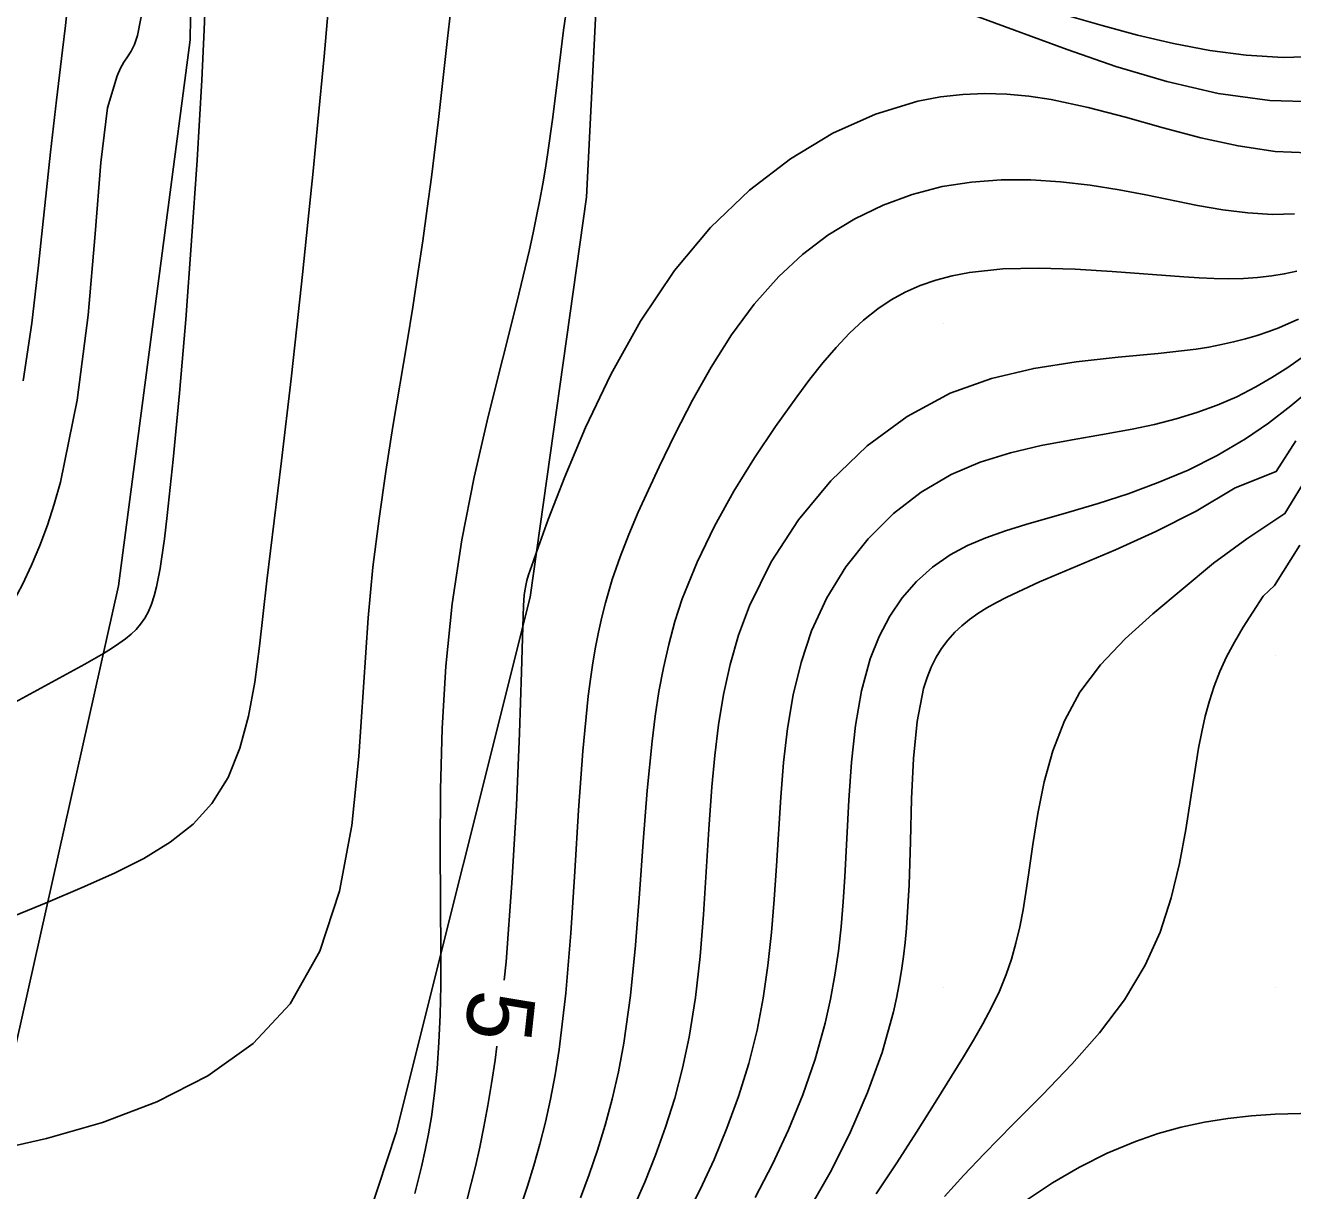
# Model space of a CAD drawing. Extents: x 2602990 to 2605851, y 618069 to 619180.
# Drawn here: x 2603422.33 to 2603460.52, y 618573.87 to 618609 of the extents above; entities that cross this region are included whole.
import ezdxf

# ---------------------------------------------------------------- set-up
doc = ezdxf.new("R2010")
doc.units = 0
for name, color, linetype in [('DTM Contours Major', 7, 'Continuous'), ('DTM Contours Minor', 7, 'Continuous'), ('DTM Contours Minor Text', 7, 'Continuous'), ('Exist DTM Crownline', 7, 'Continuous'), ('Exist DTM QL2 LIDAR Elevation Point', 7, 'Continuous'), ('Exist Roads EOP', 7, 'Continuous'), ('PH Exist DTM Breakline', 7, 'Continuous')]:
    doc.layers.add(name, color=color, linetype=linetype)

msp = doc.modelspace()

# ---------------------------------------------------------------- linework, layer by layer
at = {"layer": 'DTM Contours Major'}
msp.add_lwpolyline([(2603440.652, 618573.336), (2603440.998, 618574.125), (2603441.325, 618574.94), (2603441.627, 618575.783), (2603441.901, 618576.656), (2603442.14, 618577.56), (2603442.339, 618578.499), (2603442.527, 618579.696), (2603442.664, 618580.935), (2603442.767, 618582.202), (2603442.929, 618584.771), (2603443.021, 618586.047), (2603443.108, 618586.986), (2603443.221, 618587.912), (2603443.371, 618588.827), (2603443.57, 618589.73), (2603443.828, 618590.623), (2603444.157, 618591.505), (2603444.809, 618592.829), (2603445.631, 618594.095), (2603446.602, 618595.271), (2603447.702, 618596.321), (2603448.91, 618597.212), (2603450.207, 618597.909), (2603451.449, 618598.359), (2603452.723, 618598.662), (2603454.002, 618598.86), (2603455.261, 618598.995), (2603456.475, 618599.109), (2603457.617, 618599.244), (2603458.002, 618599.305), (2603458.377, 618599.376), (2603458.743, 618599.457), (2603459.103, 618599.549), (2603459.457, 618599.655), (2603459.807, 618599.775), (2603460.104, 618599.888), (2603460.401, 618600.013), (2603460.699, 618600.148)], dxfattribs=at)
at = {"layer": 'DTM Contours Minor'}
for points in [[(2603431.706, 618612.359), (2603431.333, 618608.062), (2603431.15, 618606.095), (2603431.004, 618604.606), (2603430.848, 618603.063), (2603430.683, 618601.491), (2603430.512, 618599.912), (2603430.338, 618598.35), (2603430.047, 618595.873), (2603429.612, 618592.259), (2603429.389, 618590.282), (2603429.247, 618589.203), (2603429.06, 618588.172), (2603428.8, 618587.207), (2603428.442, 618586.323), (2603427.956, 618585.539), (2603427.385, 618584.919), (2603426.697, 618584.376), (2603425.904, 618583.89), (2603425.017, 618583.441), (2603424.047, 618583.008), (2603423.006, 618582.571), (2603421.553, 618581.972)], [(2603421.327, 618575.073), (2603422.974, 618575.448), (2603424.653, 618575.931), (2603426.296, 618576.549), (2603427.834, 618577.332), (2603429.198, 618578.308), (2603430.317, 618579.505), (2603431.211, 618581.089), (2603431.803, 618582.904), (2603432.169, 618584.885), (2603432.384, 618586.962), (2603432.663, 618591.137), (2603432.809, 618592.668), (2603432.99, 618594.138), (2603433.194, 618595.549), (2603433.41, 618596.905), (2603433.839, 618599.459), (2603434.008, 618600.505), (2603434.164, 618601.52), (2603434.308, 618602.509), (2603434.442, 618603.477), (2603434.568, 618604.43), (2603434.781, 618606.167), (2603435.059, 618608.603), (2603435.354, 618611.228)], [(2603441.957, 618611.473), (2603442.383, 618611.443), (2603443.405, 618611.301), (2603444.481, 618611.084), (2603445.566, 618610.843), (2603446.622, 618610.59), (2603447.411, 618610.388), (2603448.173, 618610.181), (2603448.923, 618609.963), (2603449.731, 618609.712), (2603450.574, 618609.429), (2603451.047, 618609.261), (2603453.725, 618608.27), (2603455.199, 618607.762), (2603456.728, 618607.306), (2603458.283, 618606.949), (2603459.837, 618606.736), (2603461.207, 618606.695)], [(2603427.813, 618611.127), (2603427.723, 618608.866), (2603427.648, 618607.345), (2603427.509, 618604.937), (2603427.344, 618602.507), (2603427.164, 618600.138), (2603426.975, 618597.914), (2603426.787, 618595.915), (2603426.607, 618594.226), (2603426.521, 618593.521), (2603426.436, 618592.907), (2603426.391, 618592.632), (2603426.345, 618592.377), (2603426.282, 618592.075), (2603426.211, 618591.802), (2603426.131, 618591.556), (2603426.039, 618591.334), (2603425.931, 618591.132), (2603425.805, 618590.948), (2603425.672, 618590.792), (2603425.519, 618590.645), (2603425.346, 618590.503), (2603425.15, 618590.362), (2603424.93, 618590.219), (2603424.685, 618590.069), (2603424.124, 618589.747), (2603421.918, 618588.54)], [(2603422.263, 618598.281), (2603422.523, 618600.02), (2603422.732, 618601.775), (2603423.09, 618605.182), (2603423.273, 618606.743), (2603423.455, 618608.253), (2603423.541, 618609.001), (2603423.62, 618609.752)], [(2603425.714, 618608.7), (2603425.913, 618609.725)], [(2603434.073, 618573.787), (2603434.274, 618574.586), (2603434.385, 618575.089), (2603434.483, 618575.59), (2603434.567, 618576.096), (2603434.664, 618576.813), (2603434.738, 618577.557), (2603434.793, 618578.339), (2603434.829, 618579.169), (2603434.849, 618580.057), (2603434.856, 618581.013), (2603434.838, 618584.203), (2603434.846, 618585.968), (2603434.894, 618587.805), (2603435.002, 618589.682), (2603435.191, 618591.565), (2603435.487, 618593.493), (2603435.861, 618595.379), (2603436.284, 618597.211), (2603436.722, 618598.973), (2603437.146, 618600.651), (2603437.523, 618602.23), (2603437.636, 618602.745), (2603437.741, 618603.247), (2603437.837, 618603.739), (2603437.926, 618604.222), (2603438.007, 618604.697), (2603438.082, 618605.165), (2603438.223, 618606.163), (2603438.343, 618607.121), (2603438.554, 618608.857), (2603438.663, 618609.605)], [(2603452.951, 618609.518), (2603454.778, 618608.999), (2603455.852, 618608.711), (2603456.934, 618608.453), (2603458.026, 618608.244), (2603459.127, 618608.099), (2603460.238, 618608.035), (2603461.512, 618608.075)], [(2603415.719, 618585.357), (2603417.038, 618586.283), (2603418.907, 618587.851), (2603420.572, 618589.613), (2603421.941, 618591.587), (2603422.243, 618592.148), (2603422.519, 618592.726), (2603422.77, 618593.322), (2603422.998, 618593.937), (2603423.204, 618594.572), (2603423.389, 618595.227), (2603423.898, 618597.707), (2603424.225, 618600.268), (2603424.44, 618602.719), (2603424.611, 618604.866), (2603424.807, 618606.517), (2603425.097, 618607.48), (2603425.195, 618607.712), (2603425.302, 618607.893), (2603425.414, 618608.052), (2603425.523, 618608.219), (2603425.625, 618608.425), (2603425.714, 618608.7)], [(2603436.76, 618580.218), (2603436.818, 618580.775), (2603436.996, 618583.14), (2603437.129, 618585.488), (2603437.223, 618587.663), (2603437.285, 618589.509), (2603437.323, 618590.87), (2603437.343, 618591.516), (2603437.365, 618591.821), (2603437.382, 618591.953), (2603437.41, 618592.111), (2603437.449, 618592.269), (2603437.499, 618592.439), (2603437.641, 618592.855), (2603437.737, 618593.123), (2603438.092, 618594.104), (2603438.586, 618595.389), (2603439.214, 618596.879), (2603439.977, 618598.478), (2603440.87, 618600.089), (2603441.893, 618601.614), (2603442.978, 618602.908), (2603444.151, 618604.031), (2603445.388, 618604.98), (2603446.664, 618605.747), (2603447.953, 618606.327), (2603449.229, 618606.716), (2603449.91, 618606.846), (2603450.583, 618606.921), (2603451.25, 618606.946), (2603451.914, 618606.925), (2603452.578, 618606.863), (2603453.243, 618606.762), (2603454.362, 618606.525), (2603455.489, 618606.231), (2603456.621, 618605.915), (2603457.753, 618605.615), (2603458.879, 618605.365), (2603459.996, 618605.203), (2603460.985, 618605.156)], [(2603437.202, 618573.214), (2603437.469, 618574.004), (2603437.66, 618574.627), (2603437.839, 618575.27), (2603438.006, 618575.938), (2603438.159, 618576.633), (2603438.297, 618577.362), (2603438.419, 618578.127), (2603438.621, 618579.822), (2603438.772, 618581.63), (2603438.893, 618583.49), (2603439.006, 618585.342), (2603439.133, 618587.125), (2603439.295, 618588.779), (2603439.36, 618589.289), (2603439.433, 618589.78), (2603439.513, 618590.254), (2603439.602, 618590.713), (2603439.701, 618591.159), (2603439.811, 618591.593), (2603440.018, 618592.297), (2603440.255, 618592.981), (2603440.518, 618593.656), (2603440.804, 618594.327), (2603441.111, 618595.004), (2603441.435, 618595.692), (2603441.917, 618596.687), (2603442.436, 618597.698), (2603443, 618598.702), (2603443.616, 618599.675), (2603444.292, 618600.594), (2603445.036, 618601.435), (2603445.752, 618602.095), (2603446.519, 618602.674), (2603447.33, 618603.17), (2603448.179, 618603.582), (2603449.059, 618603.905), (2603449.961, 618604.139), (2603450.845, 618604.279), (2603451.738, 618604.344), (2603452.636, 618604.343), (2603453.532, 618604.285), (2603454.421, 618604.182), (2603455.298, 618604.041), (2603456.097, 618603.889), (2603457.654, 618603.574), (2603458.417, 618603.442), (2603459.171, 618603.346), (2603459.917, 618603.301), (2603460.581, 618603.315)], [(2603439.062, 618573.654), (2603439.327, 618574.361), (2603439.577, 618575.091), (2603439.809, 618575.848), (2603440.02, 618576.635), (2603440.209, 618577.457), (2603440.371, 618578.317), (2603440.573, 618579.756), (2603440.724, 618581.269), (2603440.845, 618582.825), (2603440.954, 618584.39), (2603441.071, 618585.933), (2603441.217, 618587.422), (2603441.313, 618588.181), (2603441.427, 618588.919), (2603441.562, 618589.638), (2603441.721, 618590.341), (2603441.91, 618591.031), (2603442.131, 618591.71), (2603442.574, 618592.823), (2603443.097, 618593.908), (2603443.68, 618594.956), (2603444.302, 618595.961), (2603444.943, 618596.913), (2603445.583, 618597.805), (2603445.978, 618598.333), (2603446.37, 618598.831), (2603446.765, 618599.295), (2603447.169, 618599.723), (2603447.586, 618600.111), (2603448.022, 618600.458), (2603448.426, 618600.725), (2603448.85, 618600.957), (2603449.297, 618601.156), (2603449.767, 618601.321), (2603450.262, 618601.454), (2603450.783, 618601.555), (2603451.791, 618601.661), (2603452.862, 618601.685), (2603453.97, 618601.652), (2603455.088, 618601.581), (2603457.245, 618601.416), (2603457.71, 618601.388), (2603458.163, 618601.369), (2603458.605, 618601.362), (2603459.039, 618601.371), (2603459.467, 618601.398), (2603459.892, 618601.447), (2603460.272, 618601.511), (2603460.652, 618601.595)], [(2603442.227, 618573.03), (2603442.668, 618573.907), (2603443.087, 618574.815), (2603443.475, 618575.751), (2603443.826, 618576.714), (2603444.132, 618577.702), (2603444.385, 618578.713), (2603444.569, 618579.677), (2603444.711, 618580.657), (2603444.818, 618581.65), (2603444.901, 618582.654), (2603444.968, 618583.667), (2603445.095, 618585.733), (2603445.181, 618586.776), (2603445.301, 618587.807), (2603445.471, 618588.817), (2603445.708, 618589.799), (2603446.025, 618590.745), (2603446.488, 618591.744), (2603447.06, 618592.676), (2603447.73, 618593.526), (2603448.49, 618594.283), (2603449.328, 618594.932), (2603450.234, 618595.461), (2603451.11, 618595.832), (2603452.019, 618596.115), (2603452.946, 618596.333), (2603453.877, 618596.509), (2603454.797, 618596.666), (2603455.69, 618596.829), (2603456.362, 618596.973), (2603457.011, 618597.139), (2603457.639, 618597.33), (2603458.248, 618597.551), (2603458.841, 618597.806), (2603459.418, 618598.1), (2603459.9, 618598.381), (2603460.379, 618598.692), (2603460.861, 618599.03)], [(2603444.329, 618573.667), (2603444.847, 618574.67), (2603445.327, 618575.703), (2603445.759, 618576.76), (2603446.133, 618577.834), (2603446.439, 618578.92), (2603446.599, 618579.64), (2603446.729, 618580.364), (2603446.833, 618581.093), (2603446.915, 618581.83), (2603446.979, 618582.575), (2603447.03, 618583.331), (2603447.151, 618585.642), (2603447.231, 618586.785), (2603447.351, 618587.892), (2603447.532, 618588.939), (2603447.794, 618589.908), (2603448.059, 618590.58), (2603448.381, 618591.193), (2603448.758, 618591.746), (2603449.188, 618592.238), (2603449.669, 618592.667), (2603450.198, 618593.035), (2603450.722, 618593.317), (2603451.28, 618593.557), (2603451.869, 618593.767), (2603452.484, 618593.957), (2603453.776, 618594.322), (2603454.666, 618594.586), (2603455.57, 618594.881), (2603456.475, 618595.216), (2603457.373, 618595.597), (2603458.251, 618596.033), (2603459.099, 618596.532), (2603459.791, 618597.008), (2603460.464, 618597.528), (2603461.129, 618598.084)], [(2603445.995, 618573.384), (2603446.623, 618574.494), (2603447.201, 618575.646), (2603447.714, 618576.831), (2603448.149, 618578.04), (2603448.492, 618579.264), (2603448.584, 618579.679), (2603448.665, 618580.095), (2603448.735, 618580.513), (2603448.795, 618580.934), (2603448.846, 618581.358), (2603448.888, 618581.785), (2603448.969, 618583.09), (2603449.01, 618584.401), (2603449.041, 618585.683), (2603449.096, 618586.901), (2603449.206, 618588.02), (2603449.403, 618589.006), (2603449.509, 618589.344), (2603449.634, 618589.658), (2603449.778, 618589.95), (2603449.944, 618590.221), (2603450.131, 618590.472), (2603450.341, 618590.706), (2603450.553, 618590.904), (2603450.785, 618591.091), (2603451.036, 618591.268), (2603451.308, 618591.438), (2603451.599, 618591.603), (2603451.91, 618591.764), (2603452.895, 618592.222), (2603455.18, 618593.193), (2603456.399, 618593.743), (2603457.615, 618594.36), (2603458.787, 618595.064), (2603460.029, 618595.548), (2603460.617, 618596.472)], [(2603447.975, 618573.777), (2603448.596, 618574.712), (2603449.187, 618575.633), (2603449.749, 618576.528), (2603450.601, 618577.905), (2603450.905, 618578.41), (2603451.19, 618578.906), (2603451.451, 618579.396), (2603451.685, 618579.888), (2603451.889, 618580.387), (2603452.048, 618580.855), (2603452.183, 618581.336), (2603452.298, 618581.829), (2603452.398, 618582.337), (2603452.487, 618582.859), (2603452.568, 618583.398), (2603452.698, 618584.309), (2603452.845, 618585.247), (2603453.036, 618586.194), (2603453.293, 618587.131), (2603453.643, 618588.039), (2603454.11, 618588.899), (2603454.731, 618589.726), (2603455.475, 618590.504), (2603456.31, 618591.258), (2603458.139, 618592.786), (2603459.145, 618593.524), (2603460.29, 618594.285), (2603461.034, 618595.499)], [(2603450.029, 618573.693), (2603450.613, 618574.338), (2603451.222, 618574.987), (2603452.09, 618575.868), (2603452.983, 618576.764), (2603453.867, 618577.684), (2603454.702, 618578.635), (2603455.453, 618579.627), (2603456.082, 618580.666), (2603456.529, 618581.667), (2603456.865, 618582.695), (2603457.117, 618583.733), (2603457.307, 618584.759), (2603457.604, 618586.704), (2603457.689, 618587.214), (2603457.783, 618587.706), (2603457.89, 618588.179), (2603458.013, 618588.638), (2603458.157, 618589.085), (2603458.327, 618589.521), (2603458.532, 618589.965), (2603458.767, 618590.407), (2603459.03, 618590.855), (2603459.319, 618591.313), (2603459.634, 618591.79), (2603459.976, 618592.111), (2603460.736, 618593.327)], [(2603435.645, 618573.611), (2603435.896, 618574.596), (2603436.028, 618575.183), (2603436.154, 618575.795), (2603436.273, 618576.435), (2603436.385, 618577.106), (2603436.49, 618577.809), (2603436.545, 618578.229)], [(2603452.501, 618573.588), (2603453.288, 618574.108), (2603454.1, 618574.583), (2603454.935, 618575.003), (2603455.788, 618575.359), (2603456.474, 618575.592), (2603457.168, 618575.782), (2603457.868, 618575.932), (2603458.575, 618576.047), (2603459.285, 618576.127), (2603459.997, 618576.177), (2603460.76, 618576.203), (2603462.283, 618576.227), (2603463.039, 618576.26), (2603463.79, 618576.33), (2603464.534, 618576.453), (2603465.379, 618576.679), (2603465.832, 618576.847)]]:
    msp.add_lwpolyline(points, dxfattribs=at)
at = {"layer": 'Exist DTM Crownline'}
msp.add_spline([(2603233.488, 618380.754), (2603285.185, 618400.095), (2603335.457, 618418.629), (2603390.812, 618439.069), (2603440.087, 618457.325), (2603493.996, 618477.231), (2603542.655, 618495.301), (2603600.808, 618516.867), (2603653.659, 618536.362), (2603706.222, 618555.742), (2603764.811, 618577.593), (2603823.52, 618599.847), (2603878.564, 618620.56), (2603937.951, 618643.078), (2603997.369, 618665.789), (2604036.209, 618680.665), (2604055.311, 618688.017)], degree=3, dxfattribs=at)
at = {"layer": 'Exist DTM QL2 LIDAR Elevation Point'}
for p, q in [((2603450, 618600), (2603450, 618600)), ((2603460, 618600), (2603460, 618600)), ((2603450, 618590), (2603450, 618590)), ((2603460, 618590), (2603460, 618590)), ((2603450, 618580), (2603450, 618580)), ((2603460, 618580), (2603460, 618580))]:
    msp.add_line(p, q, dxfattribs=at)
at = {"layer": 'Exist Roads EOP'}
for points in [[(2603230.17, 618389.98), (2603282.929, 618409.597), (2603332.773, 618427.868), (2603388.167, 618448.413), (2603437.203, 618466.721), (2603490.778, 618486.527), (2603539.039, 618504.558), (2603597.451, 618526.156), (2603651.053, 618545.972), (2603705.208, 618566.084), (2603762.02, 618587.183), (2603820.334, 618609.162), (2603876.341, 618629.99), (2603934.909, 618652.28), (2603996.409, 618675.568), (2604033.216, 618689.957), (2604052.01, 618697.199)], [(2604034.633, 618668.486), (2603984.89, 618650.123), (2603936.767, 618631.654), (2603888.195, 618613.335), (2603837.766, 618594.258), (2603782.918, 618573.705), (2603731.939, 618554.39), (2603671.126, 618532.171), (2603621.822, 618514.106), (2603561.545, 618491.877), (2603506.421, 618471.293), (2603452.163, 618451.33), (2603398.364, 618431.316), (2603341.431, 618410.355), (2603281.65, 618388.199), (2603223.033, 618366.475), (2603185.717, 618352.612)]]:
    msp.add_spline(points, degree=3, dxfattribs=at)
at = {"layer": 'PH Exist DTM Breakline'}
for points in [[(2603420.106, 618512.049), (2603420.211, 618516.533), (2603420.648, 618529.041), (2603420.819, 618538.47), (2603422.128, 618549.088), (2603423.344, 618553.609), (2603424.552, 618556.495), (2603427.152, 618561.197), (2603431.339, 618569.035), (2603433.508, 618575.626), (2603437.546, 618591.762), (2603439.238, 618603.824), (2603439.585, 618610.612), (2603438.591, 618626.145), (2603435.827, 618639.611), (2603430.526, 618661.513), (2603425.292, 618684.296), (2603417.979, 618715.577)], [(2603408.22, 618711.909), (2603415.864, 618676.266), (2603422.019, 618648.891), (2603426.776, 618631.517), (2603427.443, 618626.233), (2603427.478, 618620.512), (2603427.295, 618608.569), (2603425.141, 618592.108), (2603420.965, 618573.458), (2603416.114, 618558.205), (2603413.059, 618550.236), (2603411.173, 618537.294), (2603410.55, 618525.353), (2603410.291, 618510.77), (2603410.807, 618500.206), (2603412.958, 618489.948), (2603414.564, 618484.094), (2603414.609, 618480.322), (2603413.96, 618476.113), (2603411.856, 618470.088), (2603407.732, 618462.124), (2603403.683, 618456.863), (2603402.289, 618454.592)]]:
    msp.add_lwpolyline(points, dxfattribs=at)

# ---------------------------------------------------------------- texts
at = {"layer": 'DTM Contours Minor Text'}
msp.add_text('5', height=2, rotation=263.8282, dxfattribs=at).set_placement((2603435.733, 618579.98))

doc.saveas('drawing.dxf')
